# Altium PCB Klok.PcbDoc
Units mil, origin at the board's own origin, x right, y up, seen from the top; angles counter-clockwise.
Board outline 6761 x 3700 mil, 2 copper layers (Top Layer, Bottom Layer); 93 components, 127 nets, 420 pads, 96 vias.
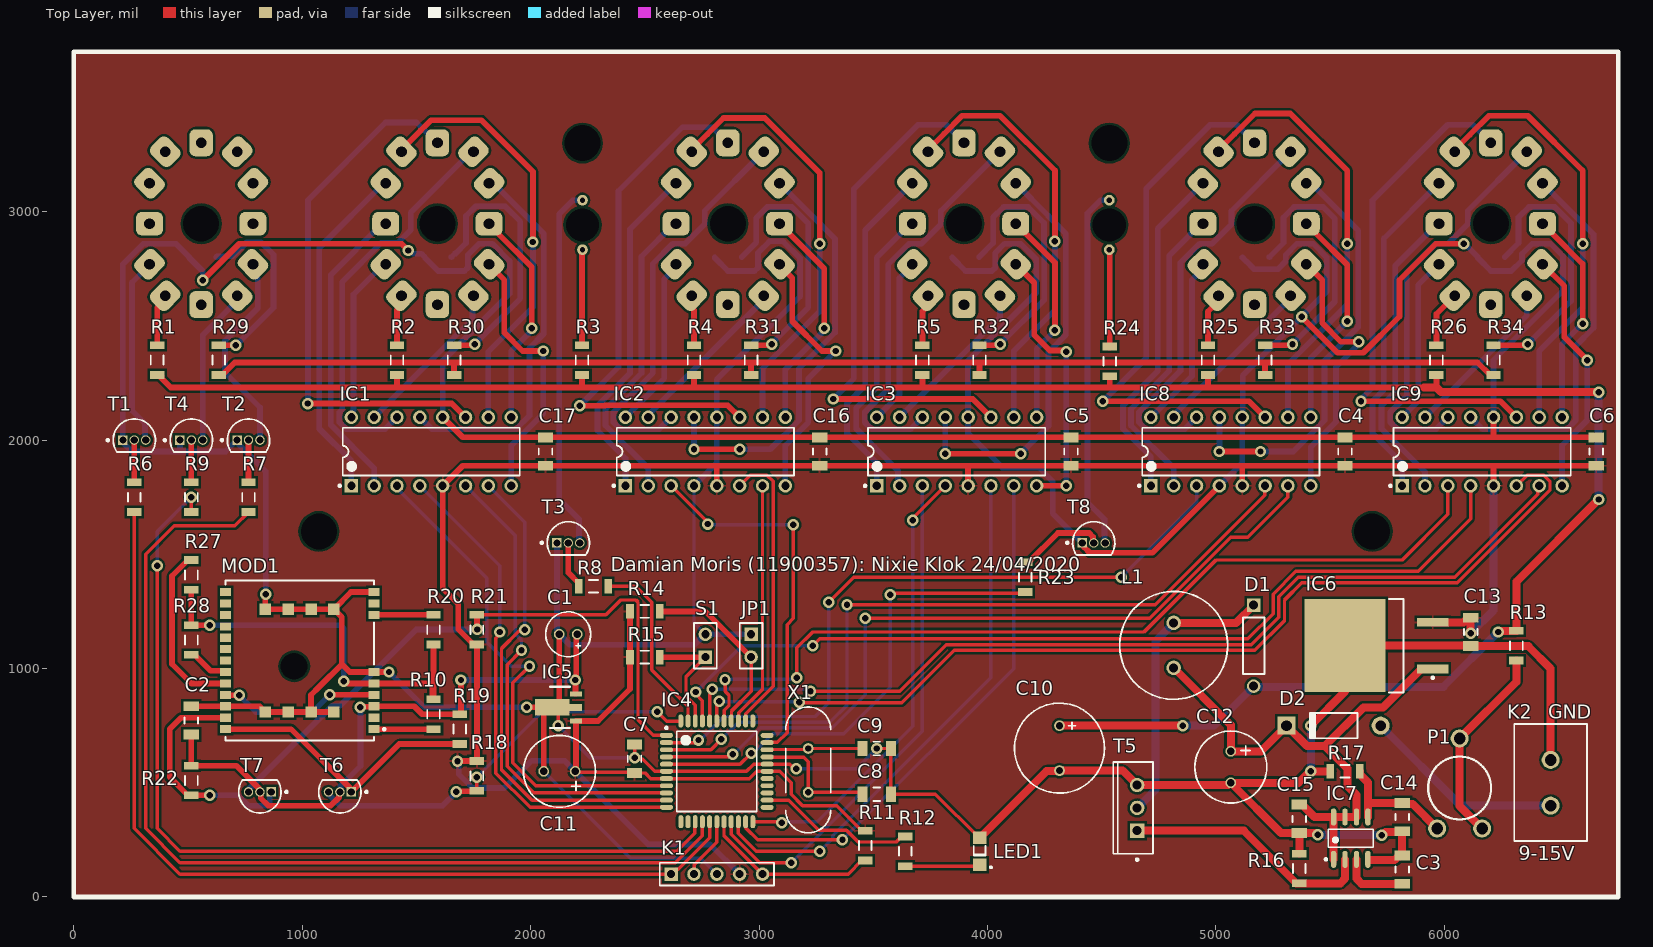
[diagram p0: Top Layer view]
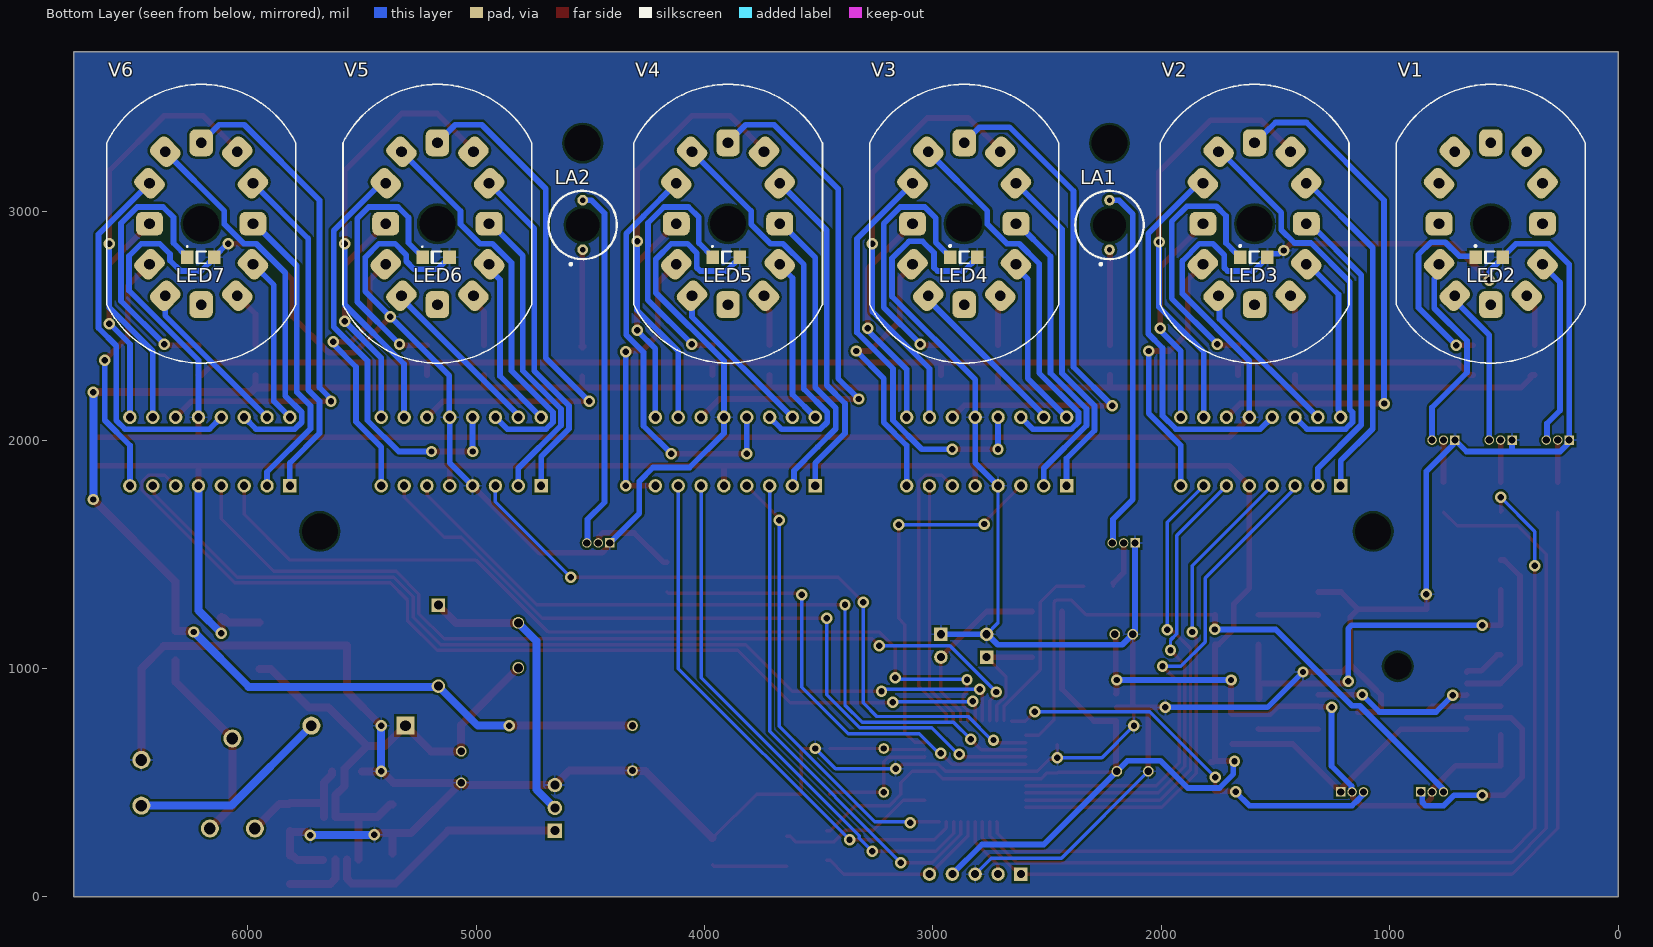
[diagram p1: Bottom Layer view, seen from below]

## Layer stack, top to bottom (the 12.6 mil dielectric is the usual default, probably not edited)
Top Solder: solder mask 0.4, Solder Resist, Dk 3.5
Top Layer: signal copper 1.4
Dielectric 1: dielectric 12.6, FR-4, Dk 4.8
Bottom Layer: signal copper 1.4
Bottom Solder: solder mask 0.4, Solder Resist, Dk 3.5

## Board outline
0,0 6761,0 6761,3700 0,3700

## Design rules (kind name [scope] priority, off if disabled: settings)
Clearance [All] p1: gap=10 ignorepadtopadclearanceinfootprint=TRUE except(0: Arc-Hole Track-Hole SMDPad-Hole THPad-Hole Via-Hole Fill-Hole Poly-Hole Region-Hole Text-Hole)
HoleSize [All] p1: absolutevalues=TRUE maxlimit=200 minlimit=1 maxpercent=80.000 minpercent=20.000
MinimumSolderMaskSliver [All] p1: minsoldermaskwidth=0.5
PolygonConnect [All] p1: connectstyle=Relief reliefconductorwidth=10 reliefentries=4 polygonreliefangle="90 Angle" airgapwidth=10
RoutingVias [All] p1: holewidth=28 width=50 viastyle="Through Hole" minholewidth=28 minwidth=50 maxholewidth=28 maxwidth=50
SilkToSolderMaskClearance [IsPad] p1: minsilkscreentomaskgap=1 clearancetoexposedcopper=TRUE
SolderMaskExpansion [All] p1: expansion=4 istentingtop=FALSE
Width [All] p1: maxlimit=35 minlimit=15 preferedwidth=25 minimp=50.000000 maximp=50.000000 favimp=50.000000
27 further rules are at their usual default settings.

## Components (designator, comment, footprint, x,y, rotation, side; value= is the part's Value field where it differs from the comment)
C1 "Cap Pol1" ELCO2.2 2165,1150 r180 top value=2,2µF
C2 "Cap" 1206_Capacitor 515,772.87 r270 top value=100nF
C3 "Cap" 1206_Capacitor 5815,120 r270 top value=680pF
C4 "Cap" 1206_Capacitor 5565,1950 r270 top value=100nF
C5 "Cap" 1206_Capacitor 4365,1950 r270 top value=100nF
C6 "Cap" 1206_Capacitor 6665,1950 r270 top value=100nF
C7 "Cap" 1206_Capacitor 2455,605 r270 top value=100nF
C8 "Cap" 1206_Capacitor 3515,450 r180 top value=22pF
C9 "Cap" 1206_Capacitor 3515,650 r180 top value=22pF
C10 "Cap Pol1" ELCO10 4315,650 r270 top value=10µF
C11 "Cap Pol1" ELCO100 2195,550 r180 top value=1µF
C12 "Cap Pol1" ELCO100 5065,637.8 r270 top value=100µF
C13 "Cap" 1206_Capacitor 6115,1160 r90 top value=100nF
C14 "Cap" 1206_Capacitor 5815,350 r90 top value=100nF
C15 "Cap" 1206_Capacitor 5365,342.13 r90 top value=100nF
C16 "Cap" 1206_Capacitor 3265,1950 r270 top value=100nF
C17 "Cap" 1206_Capacitor 2065,1950 r270 top value=100nF
D1 "BYV26" Through_Hole 5165,1100 r270 top
D2 "1N4004" DO-41 5515,750 r180 top
IC1 "K155ID1" K155ID1 1565,1950 r90 top
IC2 "K155ID1" K155ID1 2765,1950 r90 top
IC3 "K155ID1" K155ID1 3865,1950 r90 top
IC4 "PIC18F4420" PIC18F4420 2815,550 r0 top
IC5 "AP2205-33Y-13" AP2205-33Y-13 2195,830 r90 top
IC6 "7805" 7805 5562.8,1100 r180 top
IC7 "MC34063" MC34063 5590,257.48 r90 top
IC8 "K155ID1" K155ID1 5065,1950 r90 top
IC9 "K155ID1" K155ID1 6165,1950 r90 top
JP1 "Header 2" HDR1X2 2965,1150 r270 top
K1 "Header 5" HDR1X5 2615,100 r0 top
K2 "Kroonsteen" KROONSTEEN 6465,600 r270 top
L1 "Inductor" Inductor 4815,1003.15 r90 top value=330µH
LA1 "Lamp Neon" Neon_Lamp 2227,3050 r270 bottom locked
LA2 "Lamp Neon" Neon_Lamp 4533,3050 r270 bottom locked
LED1 "LED0" 1206_LED 3965,200 r90 top
LED2 "LED0" 1206_LED 565,2800 r180 bottom
LED3 "LED0" 1206_LED 1595,2800 r180 bottom
LED4 "LED0" 1206_LED 2865,2800 r180 bottom
LED5 "LED0" 1206_LED 3905,2800 r180 bottom
LED6 "LED0" 1206_LED 5175,2800 r180 bottom
LED7 "LED0" 1206_LED 6205,2800 r180 bottom
MOD1 "A2235H" A2235H 963.82,1009.8 r180 top
P1 "RPot" Pot 5968.15,300 r0 top value=500K
R1 "Res2" 1206_Resistor 365,2350 r270 top value=27K
R2 "Res2" 1206_Resistor 1415,2350 r270 top value=27K
R3 "Res2" 1206_Resistor 2225,2350 r270 top value=470K
R4 "Res2" 1206_Resistor 2715,2350 r270 top value=27K
R5 "Res2" 1206_Resistor 3715,2350 r270 top value=27K
R6 "Res2" 1206_Resistor 265,1750 r90 top value=10K
R7 "Res2" 1206_Resistor 765,1750 r90 top value=10K
R8 "Res2" 1206_Resistor 2275,1360 r180 top value=3K3
R9 "Res2" 1206_Resistor 515,1750 r90 top value=10K
R10 "Res2" 1206_Resistor 1575,800 r90 top value=10K
R11 "Res2" 1206_Resistor 3465,225 r90 top value=10K
R12 "Res2" 1206_Resistor 3640,200 r90 top value=1K
R13 "Res2" 1206_Resistor 6315,1100 r90 top value=470K
R14 "Res2" 1206_Resistor 2500,1250 r0 top value=10K
R15 "Res2" 1206_Resistor 2500,1050 r0 top value=10K
R16 "Res2" 1206_Resistor 5365,125 r270 top value=150
R17 "Res2" 1206_Resistor 5565,550 r0 top value=5K6
R18 "Res2" 1206_Resistor 1765,530 r90 top value=10K
R19 "Res2" 1206_Resistor 1690,735 r90 top value=10K
R20 "Res2" 1206_Resistor 1575,1170 r270 top value=10K
R21 "Res2" 1206_Resistor 1765,1170 r270 top value=10K
R22 "Res2" 1206_Resistor 515,510 r90 top value=10K
R23 "Res2" 1206_Resistor 4165,1400 r90 top value=3K3
R24 "Res2" 1206_Resistor 4535,2345 r270 top value=470K
R25 "Res2" 1206_Resistor 4965,2350 r270 top value=27K
R26 "Res2" 1206_Resistor 5965,2350 r270 top value=27K
R27 "Res2" 1206_Resistor 515,1410 r270 top value=2,2K
R28 "Res2" 1206_Resistor 515,1125 r90 top value=2,2K
R29 "Res2" 1206_Resistor 635,2350 r90 top value=180
R30 "Res2" 1206_Resistor 1665,2350 r90 top value=180
R31 "Res2" 1206_Resistor 2965,2350 r90 top value=180
R32 "Res2" 1206_Resistor 3965,2350 r90 top value=180
R33 "Res2" 1206_Resistor 5215,2350 r90 top value=180
R34 "Res2" 1206_Resistor 6215,2350 r90 top value=180
S1 "Switch" HDR1X2 2765,1050 r90 top
T1 "MPSA42" MPSA42 265,2000 r0 top
T2 "MPSA42" MPSA42 765,2000 r0 top
T3 "MPSA42" MPSA42 2165,1550 r0 top
T4 "MPSA42" MPSA42 515,2000 r0 top
T5 "SPP20N60C3" SPP20N60C3 4655,390 r180 top
T6 "2N7000" 2N7000 1165,460 r180 top
T7 "2N7000" 2N7000 815,460 r180 top
T8 "MPSA42" MPSA42 4465,1550 r0 top
V1 "Nixie IN12" "Nixie IN12" 556,2950 r180 bottom locked
V2 "Nixie IN12" "Nixie IN12" 1590,2950 r180 bottom locked
V3 "Nixie IN12" "Nixie IN12" 2861,2950 r180 bottom locked
V4 "Nixie IN12" "Nixie IN12" 3895,2950 r180 bottom locked
V5 "Nixie IN12" "Nixie IN12" 5167,2950 r180 bottom locked
V6 "Nixie IN12" "Nixie IN12" 6201,2950 r180 bottom locked
X1 "22.1184MHz" "XTAL - duplicate" 3215,457.87 r90 top

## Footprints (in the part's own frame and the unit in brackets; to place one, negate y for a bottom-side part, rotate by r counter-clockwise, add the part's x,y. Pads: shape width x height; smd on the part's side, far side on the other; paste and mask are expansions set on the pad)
2N7000 [mm]
  rect 1.05x1.05 hole 0.8: 1(-1.27,0)
  round 1.05 hole 0.8: 2(0,0) 3(1.27,0)
  silkscreen extent -3.08,-1.34 2.35,2.35, body extent -2.35,-1.33 2.36,2.36, height 7.87
1206_Capacitor [mm]
  rect 1.1x1.7 smd: 1(-1.578,0) 2(1.578,0)
  silkscreen extent -0.35,-0.75 0.35,0.75, body extent -1.7,-0.9 1.7,0.9, height 1.52
1206_LED [mm]
  rect 1.4x1.5 smd: 1(-1.5,0) 2(1.5,0)
  silkscreen extent -0.5,-0.67 0.6,0.65, body extent -1.6,-0.8 1.6,0.8, height 0.68
1206_Resistor [mm]
  rect 0.85x1.6 smd: 1(-1.651,0) 2(1.651,0)
  silkscreen extent -0.5,-0.7 0.5,0.7, body extent -1.6,-0.85 1.6,0.85, height 0.65
7805 [mm]
  rect 3.5x0.95 smd: 1(-9.804,2.591) 3(-9.804,-2.591)
  rect 9x10.35 smd: 4(-0.056,0)
  silkscreen extent -9.93,-5.2 -4.96,5.2, body extent -6.56,-5.2 2.79,5.2, height 4.6
A2235H [mm]
  rect 1.2x0.9 smd: 1(-8.89,6.985) 2(-8.89,5.715) 3(-8.89,4.445) 4(-8.89,3.175) 5(-8.89,1.905) 6(-8.89,0.635) 7(-8.89,-5.715) 8(-8.89,-6.985) 9(-8.89,-8.255) 10(7.62,-8.255) 11(7.62,-6.985) 12(7.62,-5.715) 13(7.62,-4.445) 14(7.62,-3.175) 15(7.62,-1.905) 16(7.62,-0.635) 17(7.62,0.635) 18(7.62,1.905) 19(7.62,3.175) 20(7.62,4.445) 21(7.62,5.715) 22(7.62,6.985)
  rect 1.27x1.27 smd: 23(-4.445,5.08) 24(-1.905,5.08) 25(0.635,5.08) 26(3.175,5.08) 27(-4.445,-6.35) 28(-1.905,-6.35) 29(0.635,-6.35) 30(3.175,-6.35)
  round 2.7 hole 3 unplated: ""(-0.03,-0.005)
  silkscreen extent -10.16,-9.53 7.62,8.26, body extent -8.89,-9.52 7.62,8.25, height 7.11
AP2205-33Y-13 [mm]
  rect 0.55x1.3 smd: 1(-1.5,-0.088) 3(1.5,-0.088)
  rect 1.85x3.825 smd: 2(0,2.54)
  rect 0.8x1.475 smd: 2(0,0)
  silkscreen extent -2.3,0.6 2.3,2.8
DO-41 [mm] "Diode, Axial; Body 5.2 x 2.7 mm (LxDia. max), Lead Dia. 0.86 mm (max)"
  round 2 hole 1.2: 1(-5.23,0)
  rect 2x2 hole 1.2: 2(5.23,0)
  silkscreen extent -2.65,-1.4 2.75,1.4
ELCO2.2 [mm]
  round 1.2 hole 0.8: 1(-0.984,0) 2(1.016,0)
  silkscreen extent -2.48,-2.5 2.51,2.5
ELCO10 [mm]
  round 1.2 hole 0.8: 1(-2.54,0) 2(2.46,0)
  silkscreen extent -5.04,-5 4.96,5
ELCO100 [mm]
  round 1.2 hole 0.8: 1(0,0) 2(3.5,0)
  silkscreen extent -2.25,-4 5.75,4
HDR1X2 [mm] "Connector; Header; 2 Position"
  rect 1.5x1.5 hole 0.9: 1(0,0)
  round 1.5 hole 0.9: 2(2.54,0)
  silkscreen extent -1.27,-1.27 3.81,1.27
HDR1X5 [mm] "Connector; Header; 5 Position"
  rect 1.5x1.5 hole 0.9: 1(0,0)
  round 1.5 hole 0.9: 2(2.54,0) 3(5.08,0) 4(7.62,0) 5(10.16,0)
  silkscreen extent -1.27,-1.27 11.43,1.27
Inductor [mm]
  round 1.6 / inner round 1.2 / far side round 1.3 hole 1: 1(0,0) 2(5,0)
  silkscreen extent -3.5,-6 8.5,6
K155ID1 [mm]
  rect 1.5x1.5 hole 0.9: 1(-3.81,8.89)
  round 1.5 hole 0.9: 2(-3.81,6.35) 3(-3.81,3.81) 4(-3.81,1.27) 5(-3.81,-1.27) 6(-3.81,-3.81) 7(-3.81,-6.35) 8(-3.81,-8.89) 9(3.81,-8.89) 10(3.81,-6.35) 11(3.81,-3.81) 12(3.81,-1.27) 13(3.81,1.27) 14(3.81,3.81) 15(3.81,6.35) 16(3.81,8.89)
  silkscreen extent -3.93,-9.85 2.65,10.31, body extent -3.95,-9.85 3.95,9.85, height 5.08
KROONSTEEN [mm]
  round 2 / inner round 1.2 / far side round 2 hole 1.3: 1(0,0) 2(5.08,0)
  silkscreen extent -4,-4.05 9,4.05
MC34063 [mm]
  oval 1.9x0.6 smd: 1(-2.35,1.905) 2(-2.35,0.635) 3(-2.35,-0.635) 4(-2.35,-1.905) 5(2.35,-1.905) 6(2.35,-0.635) 7(2.35,0.635) 8(2.35,1.905)
  silkscreen extent -2.47,-2.5 1,2.88, body extent -2,-2.5 2,2.5, height 1.75
MPSA42 [mm]
  rect 1.05x1.05 hole 0.8: 1(-1.27,0)
  round 1.05 hole 0.8: 2(0,0) 3(1.27,0)
  silkscreen extent -3.07,-1.34 2.35,2.35, body extent -2.35,-1.33 2.36,2.36, height 7.87
Neon_Lamp [mm]
  round 1.2 hole 0.6: 1(0,0) 2(5.5,0)
  round 1.524 hole 3.7: 3(2.75,0)
  silkscreen extent -1.05,-3.8 6.55,3.8
"Nixie IN12" [mm]
  rrect50% 0x0 hole 4 unplated: 0(-0.05,-0.075)
  rrect50% 2.6x3 hole 1.2 rot 45: 1(3.95,-8.075) 2(5.7,-4.575) 7(-4.05,7.925) 8(-5.8,4.425)
  rrect50% 3x2.6 hole 1.2: 3(5.7,-0.075) 9(-5.8,-0.075)
  rrect50% 2.6x3 hole 1.2 rot 135: 4(5.7,4.425) 5(3.95,7.925) 10(-5.8,-4.575) 11(-4.05,-8.075)
  rrect50% 2.6x3 hole 1.2: 6(-0.05,8.925) 12(-0.05,-9.075)
  silkscreen extent -10.55,-15.58 10.45,15.42
PIC18F4420 [mm]
  oval 1.45x0.55 smd: 1(-5.6,4) 2(-5.6,3.2) 3(-5.6,2.4) 4(-5.6,1.6) 5(-5.6,0.8) 6(-5.6,0) 7(-5.6,-0.8) 8(-5.6,-1.6) 9(-5.6,-2.4) 10(-5.6,-3.2) 11(-5.6,-4) 23(5.6,-4) 24(5.6,-3.2) 25(5.6,-2.4) 26(5.6,-1.6) 27(5.6,-0.8) 28(5.6,0) 29(5.6,0.8) 30(5.6,1.6) 31(5.6,2.4) 32(5.6,3.2) 33(5.6,4)
  oval 0.55x1.45 smd: 12(-4,-5.6) 13(-3.2,-5.6) 14(-2.4,-5.6) 15(-1.6,-5.6) 16(-0.8,-5.6) 17(0,-5.6) 18(0.8,-5.6) 19(1.6,-5.6) 20(2.4,-5.6) 21(3.2,-5.6) 22(4,-5.6) 34(4,5.6) 35(3.2,5.6) 36(2.4,5.6) 37(1.6,5.6) 38(0.8,5.6) 39(0,5.6) 40(-0.8,5.6) 41(-1.6,5.6) 42(-2.4,5.6) 43(-3.2,5.6) 44(-4,5.6)
  silkscreen extent -5.72,-4.45 4.45,4.95, body extent -5,-5 5,5, height 1.2
Pot [mm]
  round 2 / inner round 1.2 / far side round 2 hole 1.3: 1(2.5,10) 2(0,0) 3(5,0)
  silkscreen extent -1,1 6,8
SPP20N60C3 [mm]
  rect 1.6x1.6 hole 1: 1(0,2.54)
  round 1.6 hole 1: 2(0,0) 3(0,-2.54)
  silkscreen extent -1.75,-5.1 2.65,5.87, body extent -1.75,-5.1 2.65,5.1, height 20.7
Through_Hole [mm]
  rect 1.5x1.5 hole 1: 1(-4.5,0)
  round 1.5 hole 1: 2(4.5,0)
  silkscreen extent -3.15,-1.2 3.15,1.2, body extent -3.15,-1.2 3.15,1.2, height 2.4
"XTAL - duplicate" [mm]
  round 1.2 hole 0.7: 1(0,0) 2(4.88,0)
  silkscreen extent -4.5,-2.5 9.5,2.5

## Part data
C1 C10 C11 C12: "Polarized Capacitor (Radial)"
C2 C3 C4 C5 C6 C7 C8 C9 C13 C14 C15 C16 C17: "Capacitor"
D2: library part "Diode 1N4004", "1 Amp General Purpose Rectifier"
JP1: "Header, 2-Pin"
K1: "Header, 5-Pin"
K2 S1: library part "Header 2", "Header, 2-Pin"
LA1 LA2: "Neon Lamp"
LED1 LED2 LED3 LED4 LED5 LED6 LED7: "Typical INFRARED GaAs LED"
P1: "Potentiometer"
R1 R2 R3 R4 R5 R6 R7 R8 R9 R10 R11 R12 R13 R14 R15 R16 R17 R18 R19 R20 R21 R22 R23 R24 R25 R26 R27 R28 R29 R30 R31 R32 R33 R34: "Resistor"
X1: library part XTAL, "Crystal Oscillator"

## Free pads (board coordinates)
  round 60 hole 157.48 unplated: 4(1073,1600) 4(2227,3300) 4(4533,3300) 4(5684,1600)

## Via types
v1: diameter 50, hole 28, Top Layer to Bottom Layer, 96 vias

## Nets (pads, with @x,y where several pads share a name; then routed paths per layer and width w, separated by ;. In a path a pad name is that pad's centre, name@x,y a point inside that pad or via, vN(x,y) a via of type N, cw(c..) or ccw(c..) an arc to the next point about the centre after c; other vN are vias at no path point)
+1.8V: MOD1.5 R10.2 R20.2 R27.2 R28.2 | length 1754.3
  Top Layer w25: R27.2 R28.2 v1(595,1190) ; v1(1182.47,944.64) 1189.23,944.64 1199.07,934.8 MOD1.5 ; MOD1.5@1319.72,934.8 1565.2,934.8 1570,930 1570,869.23 1574.23,865 R10.2 R20.2
  Bottom Layer w25: v1(595,1190) 1167.57,1190 1182.22,1175.36 1182.22,944.89 v1(1182.47,944.64)
+3,3V: C1.1 C2.2 IC5.3 MOD1.3 R19.2 R22.2 T6.2 T7.2 | length 2691.6
  Top Layer w25: C2.2 R22.2 711.05,575 811.87,474.18 811.87,463.13 818.13,456.87 818.13,433.72 851.84,400 1125,400 1161.87,436.87 1161.87,456.87 T6.2 ; v1(1255,830) 1257.4,832.4 1311.42,832.4 MOD1.3 1490.46,834.8 1525.27,800 R19.2 1695,805 v1(1695,950) ; IC5.3 2196.72,890.73 2196.72,948.28 v1(2195,950) 2199.48,954.48 2199.48,1145.74 C1.1
  Bottom Layer w25: T6.2 1168.13,463.13 1168.13,486.28 1255,573.16 v1(1255,830) ; v1(1695,950) v1(2195,950)
+3.3V: R29.1 R30.1 R31.1 R32.1 R33.1 R34.1 | length 5845.6
  Top Layer w25: R29.1 649.76,2285 704.76,2340 1665,2340 ; R30.1 1665,2340 ; R31.1 2965,2340 ; R32.1 3965,2340 ; R33.1 5215,2340 ; R34.1 6200.24,2285 6145.24,2340 5215,2340 ; 1665,2340 2965,2340 ; 2965,2340 3965,2340 ; 3965,2340 5215,2340
+5V: C4.2 C5.2 C6.2 C7.2 C11.1 C13.2 C16.2 C17.2 IC1.5 IC2.5 IC3.5 IC4.7 IC4.28 IC5.1 IC6.3 IC8.5 IC9.5 K1.4 R11.2 R14.1 R15.1 R18.2 R21.2 | length 11606.5
  Top Layer w15: C11.1 2198.56,546.44 2451.44,546.44 C7.2@2455.05,542.82 ; C7.2 C7.2@2455.05,542.82 ; IC4.7 2526.5,518.5 2502.18,542.82 C7.2@2455.05,542.82 ; IC4.7@2595.8,517.23 2957.23,517.23 2990,550 IC4.28 3090,550 3140,500 3140,450 3190,400 3340.24,400 3450.24,290 R11.2
  Top Layer w25: v1(1680,595) R18.2 R21.2 1750.24,1105 1683.76,1171.48 1683.76,1281.24 1615,1350 IC1.5 1702.87,1887.87 C17.2 2815,1887.87 ; R18.2@1770,595 1774.23,590.77 R18.2@1784,590.77 ; C11.1@2198.44,550 IC5.1 2199.39,770 2295,770 2435,910 R15.1 R14.1 ; IC2.5 2815,1887.87 ; IC3.5 3915,1887.87 ; IC8.5 5115,1887.87 ; IC9.5 6215,1887.87 ; C6.2 6215,1887.87 ; 2815,1887.87 C16.2 3915,1887.87 ; 3915,1887.87 C5.2 5115,1887.87 ; 5115,1887.87 C4.2 6215,1887.87
  Top Layer w35: IC6.3 6083.06,1202 6103.19,1222.13 C13.2 v1(6115,1154.53) ; C13.2@6115,1226.28 C13.2@6119.15,1222.13
  Bottom Layer w25: v1(1680,595) 1684.78,590.22 1684.78,538.04 1745.32,477.5 1884.78,477.5 2003.4,596.12 2148.88,596.12 C11.1 2515,230 2785,230 K1.4
  Bottom Layer w35: v1(6115,1154.53) 6215,1254.53 IC9.5
+180V: C10.1 D1.2 R1.2 R2.2 R3.2 R4.2 R5.2 R13.2 R24.2 R25.2 R26.2 | length 10105.3
  Top Layer w25: R1.2 379.76,2285 384,2280.77 384,2271 425,2230 1415,2230 ; R2.2 1415,2230 ; R3.2 2225,2230 ; R4.2 2715,2230 ; R5.2 3715,2230 ; R24.2 4535,2230 ; R25.2 4965,2240 4975,2230 ; 5911.36,2230 4975,2230 ; 5965,2230 R26.2 ; 1415,2230 2225,2230 ; 2225,2230 2715,2230 ; 2715,2230 3715,2230 ; 3715,2230 4535,2230 ; 4535,2230 4965,2230 4975,2230
  Top Layer w35: C10.1 v1(4855,750) ; D1.2 5167.83,920 D1.2@5169.25,921.42 ; 5911.36,2230 5965,2230 5985,2210 v1(6675,2210) ; v1(6235,1160) 6239.06,1160 6244.06,1165 R13.2 6315,1380 v1(6675,1740)
  Bottom Layer w35: v1(4855,750) 4992.17,750 D1.2 5167.83,920 5995,920 v1(6235,1160) ; v1(6675,1740) v1(6675,2210)
GND: C1.2 C2.1 C3.1 C4.1 C5.1 C6.1 C7.1 C8.1 C9.1 C10.2 C11.2 C12.2 C13.1 C14.1 C15.1 C16.1 C17.1 IC1.12 IC2.4 IC2.12 IC3.12 IC4.6 IC4.29 IC5.2 IC6.4 IC7.4 IC8.4 IC8.12 IC9.12 JP1.1 K1.3 K2.1 LED1.2 LED2.2 LED3.2 LED4.2 LED5.2 LED6.2 LED7.2 MOD1.6 MOD1.9 MOD1.20 MOD1.23 MOD1.24 MOD1.25 MOD1.26 MOD1.27 MOD1.28 MOD1.29 MOD1.30 R16.1 R17.1 S1.2 T1.1 T2.1 T3.1 T4.1 T5.3 T8.1 | length 32496
  Top Layer w15: v1(2120,750) IC5.2@2120,830 ; C7.1 v1(2455,610) 2461.7,603.3 2490.18,603.3 2543.48,550 IC4.6 2945,550 2976.5,581.5 3133.5,581.5 3146.76,568.24 3156.86,568.24 v1(3163.56,561.55) ; v1(3514.95,650.05) 3515,650 C9.1 C8.1 3772.09,450 3963.03,259.06 LED1.2
  Top Layer w25: C2.1 515.1,834.9 663.72,834.9 663.82,835 813.62,835 MOD1.26 MOD1.25 MOD1.24 ; v1(565,2700) 724.73,2859.73 1435.27,2859.73 v1(1465,2830) ; v1(840,1325) 838.82,1323.82 MOD1.30 MOD1.29 MOD1.28 MOD1.27 ; MOD1.23 MOD1.24 ; MOD1.9 1213.82,1334.8 MOD1.27 ; v1(1380.2,984.8) MOD1.6 1207.83,984.8 1173.82,1018.82 ; IC1.12 1702.87,2012.13 C17.1 C16.1 C5.1 C4.1 6215,2012.13 ; v1(1982.5,830) IC5.2@2055,830 ; C11.2 2057.2,822.03 2060.65,825.47 2056.12,830 2095,830 2115,830 2125,840 C1.2 ; IC5.2@2120,830 IC5.2@2195,830 ; T8.1 4421.83,1543.17 4421.83,1532.12 4447.12,1506.83 4721.83,1506.83 IC8.4 ; v1(5375,2540) 5532.5,2382.5 5644.68,2382.5 5803.46,2541.28 5803.46,2700.95 5962.51,2860 v1(6085,2860) ; IC9.12 6215,2012.13 ; C6.1 6215,2012.13 ; MOD1.24 1038.82,883.82 1075,920 1173.82,1018.82 ; MOD1.27 1173.82,1224.8 1173.82,1018.82
  Top Layer w35: LED1.2 3966.97,259.06 4258.72,550.81 4312.66,550.81 C10.2 4591.85,553.15 T5.3 5051.69,490 5061.69,500 C12.2 ; R16.1 C15.1 ; v1(5415,750) 5565,900 IC6.4 6112.87,1100 C13.1 6367.13,1097.87 6465,1000 K2.1 ; v1(5445,272.13) 5437.13,280 C15.1 ; R17.1 v1(5415,550) 5410.94,550 5360.94,500 C12.2 ; IC7.4@5670.69,161.29 5782.35,161.29 5803.19,182.13 C3.1 C14.1 5810.85,283.72 5742.78,283.72 5729.06,270 v1(5725,270) ; C12.2 5285,280 C15.1
  Bottom Layer w15: C11.2 2437.2,170 2745,170 K1.3 ; v1(2120,750) 2260,610 v1(2455,610) ; IC2.4 2715,1200 S1.2 ; v1(3163.56,561.55) 3426.44,561.55 v1(3514.95,650.05)
  Bottom Layer w25: T4.1 465,1955.53 459.47,1950 ; v1(565,2700) 565,2738.98 505.94,2798.03 LED2.2 505.94,2801.97 448.18,2859.73 304.73,2859.73 215,2770 T1.1 221.83,1993.17 221.83,1982.12 253.95,1950 459.47,1950 ; v1(840,1325) 840,1863.95 721.83,1982.12 721.83,1993.17 T2.1 665,1950 459.47,1950 ; v1(1380.2,984.8) 1535,830 v1(1982.5,830) ; v1(1465,2830) 1471.76,2830 1485.45,2816.32 1520.89,2816.32 1535.94,2801.26 LED3.2 1595.94,2740 1710.36,2740 1725,2754.64 1725,2810 1775,2860 1832.43,2860 1908.2,2784.23 1908.2,2640.37 1615,2347.18 IC1.12 ; T3.1 2115,1166.02 2125,1156.02 C1.2 2171.12,1103.88 2716.33,1103.88 2762.45,1150 S1.2 JP1.1 ; IC2.4 2815,1900 IC2.12 2815,2264.63 3179.2,2628.82 3179.2,2795.8 3105,2870 3045,2870 2995,2820 2995,2754.64 2980.36,2740 2863.98,2740 2805.94,2798.03 LED4.2 ; LED5.2 3845.94,2798.03 3903.98,2740 4018.85,2740 4033.5,2754.64 4033.5,2818.5 4075,2860 4145,2860 4213.2,2791.8 4213.2,2645.37 3915,2347.18 IC3.12 3915,2030 4065,1880 4225,1880 4285,1820 4285,1680 T8.1 ; IC8.4 5115,1900 IC8.12 5117.4,2102.4 5117.4,2282.4 v1(5375,2540) 5485.2,2650.2 5485.2,2799.8 5425,2860 5355,2860 5305.5,2810.5 5305.5,2782.54 5270.93,2747.97 5197.18,2747.97 ; LED6.2 5115.94,2798.03 5131,2782.97 5132.97,2782.97 5167.94,2748.01 5197.14,2748.01 ; v1(6085,2860) 6087.91,2860 6145.94,2801.97 LED7.2 6145.94,2798.03 6203.98,2740 6292.96,2740 6339.5,2786.54 6339.5,2814.5 6385,2860 6465,2860 6519.2,2805.8 6519.2,2654.2 6215,2350 IC9.12
  Bottom Layer w35: v1(5415,550) v1(5415,750) ; v1(5445,272.13) 5446.06,271.06 5723.94,271.06 v1(5725,270)
NetC3_2: C3.2 IC7.3 | length 293.8
  Top Layer w35: IC7.3 5615,80.5 5637.63,57.87 C3.2
NetC8_2: C8.2 IC4.30 X1.1 | length 563.4
  Top Layer w15: IC4.30 3036.75,611.72 3195.13,611.72 3215,591.84 X1.1 3445,457.87 C8.2
NetC9_2: C9.2 IC4.31 X1.2 | length 419.7
  Top Layer w15: IC4.31 3036.75,645.76 3210.76,645.76 X1.2 C9.2
NetC12_1: C12.1 C15.2 D2.2 IC6.1 IC7.1 IC7.6 IC7.7 IC7.8 L1.1 | length 2399.2
  Top Layer w35: L1.1 5065,753.15 C12.1 5196.89,637.8 D2.2 5398.59,660.51 5476.61,660.51 ; C15.2 5376.81,404.25 5431.06,350 IC7.7 IC7.6 5615,446.01 5575,486.01 5575,562.12 5476.61,660.51 ; IC7.1 IC7.8@5515,347.82 ; IC6.1 5898.6,998 5730.6,830 5646.1,830 5476.61,660.51
NetC14_2: C14.2 IC7.5 P1.2 R17.2 | length 565
  Top Layer w35: R17.2 5630,536.77 5665,501.77 5665,410 ; IC7.5 5665,410 ; P1.2 5860.18,407.97 5819.15,407.97 C14.2 5667.13,412.13 5665,410
NetD1_1: D1.1 L1.2 T5.2 | length 1258.2
  Top Layer w35: L1.2 5087.83,1200 D1.1
  Bottom Layer w35: T5.2 4736.13,471.13 4736.13,1121.13 L1.2
NetD2_1: D2.1 K2.2 | length 889.1
  Bottom Layer w35: D2.1 6070.91,400 K2.2
NetIC1_1: IC1.1 V2.4 | length 1503.2
  Bottom Layer w25: IC1.1 1215,1910 1075,2050 1075,2842.17 V2.4@1360,3127.17
NetIC1_2: IC1.2 V2.3 | length 1330.7
  Bottom Layer w25: IC1.2 1315,1876.92 1125,2066.92 1125,2722.87 1352.13,2950 V2.3@1360,2950
NetIC1_3: IC1.3 IC4.8 | length 2243.4
  Top Layer w15: v1(1995,1010) 1922.5,937.5 1922.5,587.5 2022.99,487.01 IC4.8
  Bottom Layer w15: IC1.3 1415,1790 1808.59,1396.41 1808.59,1116.31 1914.9,1010 v1(1995,1010)
NetIC1_4: IC1.4 IC4.11 | length 2218.8
  Top Layer w15: v1(1864.95,1160.05) 1864.95,1150.58 1847.5,1133.13 1847.5,542.5 1997.48,392.52 IC4.11
  Bottom Layer w15: IC1.4 1864.95,1450.05 v1(1864.95,1160.05)
NetIC1_6: IC1.6 IC4.9 | length 2100.4
  Top Layer w15: v1(1960,1080) 1897.5,1017.5 1897.5,572.5 2014.49,455.51 IC4.9
  Bottom Layer w15: IC1.6 1932.5,1582.5 1932.5,1152.4 1960,1124.9 v1(1960,1080)
NetIC1_7: IC1.7 IC4.10 | length 2140.3
  Top Layer w15: v1(1975,1170) 1968.3,1163.3 1948.2,1163.3 1872.5,1087.6 1872.5,557.5 2005.98,424.02 IC4.10
  Bottom Layer w15: IC1.7 1975,1640 v1(1975,1170)
NetIC1_8: IC1.8 V2.10 | length 1183.9
  Top Layer w25: V2.10@1812.76,2772.83 1885,2700.59 1885,2470 1965,2390 v1(2055,2390)
  Bottom Layer w25: IC1.8 1915,1976.92 2055,2116.92 v1(2055,2390)
NetIC1_9: IC1.9 V2.9 | length 967.4
  Top Layer w25: V2.9@1812.76,2950 1813.55,2950 1851.23,2912.32 1851.23,2911.53 2005,2757.76 v1(2005,2490)
  Bottom Layer w25: IC1.9 1915,2390 2005,2480 v1(2005,2490)
NetIC1_10: IC1.10 V2.5 | length 1886.2
  Top Layer w25: V2.5@1428.9,3264.96 1518.29,3354.35 1518.29,3354.76 1546.46,3382.93 1546.87,3382.93 1563.94,3400 1785,3400 2010,3175 v1(2010,2867)
  Bottom Layer w25: IC1.10 1815,2387.23 2010,2582.23 v1(2010,2867)
NetIC1_11: IC1.11 V2.6 | length 2343
  Top Layer w25: v1(1025,2160) 1655,2160 IC1.11
  Bottom Layer w25: v1(1025,2160) 1025,3050 1365,3390 1500.71,3390 1547.9,3342.8 1548.69,3342.8 1586.38,3305.12 V2.6@1586.38,3304.33
NetIC1_13: IC1.13 V2.8 | length 1679.6
  Bottom Layer w25: IC1.13 1567.03,2047.97 1936.55,2047.97 1995,2106.42 1995,2402.82 2057.5,2465.32 2057.5,2904 1995,2966.5 1837.28,3124.21 V2.8
NetIC1_14: IC1.14 V2.7 | length 1755.5
  Bottom Layer w25: IC1.14 1362.97,2047.97 1193.45,2047.97 1162.97,2078.45 1162.97,2121.55 1175,2133.58 1175,2692.04 1345.65,2862.68 1417.68,2862.68 1475,2920 1475,2996.1 V2.7@1743.86,3264.96
NetIC1_15: IC1.15 V2.11 | length 713.8
  Bottom Layer w25: IC1.15 1745.19,2530.19 1745.19,2633.71 V2.11@1743.86,2635.04
NetIC1_16: IC1.16 V2.2 | length 732.9
  Bottom Layer w25: IC1.16 1221.52,2106.52 1221.52,2128.19 1225,2131.67 1225,2637.83 V2.2@1360,2772.83
NetIC2_1: IC2.1 V3.4 | length 1517.1
  Bottom Layer w25: IC2.1 2415,1920 2292.97,2042.03 2292.97,2150.55 2435,2292.57 2435,2922.62 V3.4
NetIC2_2: IC2.2 V3.3 | length 1357
  Bottom Layer w25: IC2.2 2515,1876.92 2327.97,2063.95 2327.97,2136.05 2485,2293.08 2485,2803.33 2628.72,2947.05 V3.3
NetIC2_3: IC2.3 IC4.32 | length 1637.3
  Top Layer w15: IC2.3 2775,1640 v1(2775,1632.5) ; IC4.32 3036.75,677.26 3080.38,677.26 3122.45,719.33 3122.45,1192.45 3150.3,1220.3 v1(3150.3,1630)
  Bottom Layer w15: v1(2775,1632.5) 2777.5,1630 v1(3150.3,1630)
NetIC2_6: IC2.6 IC4.35 | length 1277.1
  Top Layer w15: IC2.6 2962.03,1847.03 3034.48,1847.03 3062.03,1819.48 3062.03,921.67 2942.26,801.9 2942.26,771.75 IC4.35
NetIC2_7: IC2.7 IC4.36 | length 1073.2
  Top Layer w15: IC4.36 2910.76,771.75 2910.76,805.76 3015,910 IC2.7
NetIC2_8: IC2.8 V3.10 | length 1197.9
  Top Layer w25: V3.10 3089.35,2765.35 3145,2709.7 3145,2520 3275,2390 v1(3335,2390)
  Bottom Layer w25: IC2.8 3115,1976.92 3215,2076.92 3215,2270 v1(3335,2390)
NetIC2_9: IC2.9 V3.9 | length 999
  Top Layer w25: V3.9 3090.14,2947.05 3127.82,2909.36 3127.82,2908.57 3285,2751.39 v1(3285,2490)
  Bottom Layer w25: IC2.9 3115,2310 3285,2480 v1(3285,2490)
NetIC2_10: IC2.10 V3.5 | length 1899
  Top Layer w25: V3.5 2705.49,3270.49 2774.8,3339.8 2774.8,3340.27 2844.53,3410 3025,3410 3265,3170 v1(3265,2860)
  Bottom Layer w25: IC2.10 3015,2312.82 3265,2562.82 v1(3265,2860)
NetIC2_11: IC2.11 V3.6 | length 2355.6
  Top Layer w25: v1(2215,2150) 2325,2150 2327.03,2152.03 2862.97,2152.03 IC2.11
  Bottom Layer w25: v1(2215,2150) 2385,2320 2385,3090 2665,3370 2795.14,3370 2862.97,3302.17 V3.6
NetIC2_13: IC2.13 V3.8 | length 1856.1
  Top Layer w25: v1(2715,1960) v1(2915,1960)
  Bottom Layer w25: v1(2715,1960) IC2.13 ; v1(2915,1960) 3048.58,1960 3175,2086.42 3175,2312.82 3332.5,2470.32 3332.5,2881.06 V3.8
NetIC2_14: IC2.14 V3.7 | length 1773.8
  Bottom Layer w25: IC2.14 2562.97,2047.97 2393.45,2047.97 2362.97,2078.45 2362.97,2121.55 2535,2293.58 2535,2772.49 2622.24,2859.73 2676.34,2859.73 2761.73,2945.12 2761.73,3003.29 V3.7
NetIC2_15: IC2.15 V3.11 | length 741.5
  Bottom Layer w25: IC2.15 2515,2109.22 3020.45,2614.66 V3.11
NetIC2_16: IC2.16 V3.2 | length 761.7
  Bottom Layer w25: IC2.16 2585,2270 2585,2705.63 2636.59,2757.22 V3.2
NetIC3_1: IC3.1 V4.4 | length 1496.4
  Bottom Layer w25: IC3.1 3515,1900 3385,2030 3385,2160 3465,2240 3465,2918.62 V4.4
NetIC3_2: IC3.2 V4.3 | length 1332.1
  Bottom Layer w25: IC3.2 3608.48,1806.52 3608.48,1865.73 3505,1969.22 3505,1970 3425,2050 3425,2140 3515,2230 3515,2799.33 3662.72,2947.05 V4.3
NetIC3_3: IC3.3 IC4.19 | length 2256.7
  Top Layer w15: IC4.19 2877.99,274.62 3002.62,150 v1(3140,150)
  Bottom Layer w15: v1(3140,150) 3715,725 IC3.3
NetIC3_4: IC3.4 IC4.22 | length 1988.5
  Top Layer w15: IC4.22 3094.53,329.53 3099.11,324.95 v1(3100.05,324.95) ; v1(3672.5,1650) 3672.5,1657.5 IC3.4
  Bottom Layer w15: v1(3100.05,324.95) 3105.1,330 3255,330 3672.5,747.5 v1(3672.5,1650)
NetIC3_6: IC3.6 IC4.20 | length 2349.7
  Top Layer w15: IC4.20 2909.49,278.48 2987.97,200 v1(3265,200)
  Bottom Layer w15: v1(3265,200) 3322.5,257.5 3322.5,267.6 4015,960.1 IC3.6
NetIC3_7: IC3.7 IC4.21 | length 2333
  Top Layer w15: IC4.21 2942.26,328.25 2942.26,301.97 2994.23,250 v1(3365,250)
  Bottom Layer w15: v1(3365,250) 4115,1000 IC3.7
NetIC3_8: IC3.8 V4.10 | length 1231.2
  Top Layer w25: V4.10 4204.62,2688.6 4204.62,2460.38 4272.72,2392.28 4340.22,2392.28 v1(4345,2387.5) ; IC3.8 v1(4345,1800)
  Bottom Layer w25: v1(4345,1800) v1(4345,2387.5)
NetIC3_9: IC3.9 V4.9 | length 951.7
  Top Layer w25: V4.9 4124.14,2947.05 4295,2776.18 v1(4295,2480)
  Bottom Layer w25: IC3.9 4215,2400 v1(4295,2480)
NetIC3_10: IC3.10 V4.5 | length 1880.2
  Top Layer w25: V4.5 3739.49,3270.96 3808.8,3340.27 3888.53,3420 4055,3420 4295,3180 v1(4295,2870)
  Bottom Layer w25: IC3.10 4115,2389.61 4295,2569.61 v1(4295,2870)
NetIC3_11: IC3.11 V4.6 | length 2311.4
  Top Layer w25: v1(3325,2180) 3935,2180 IC3.11
  Bottom Layer w25: v1(3325,2180) 3415,2270 3415,3100 3695,3380 3819.14,3380 3896.97,3302.17 V4.6
NetIC3_13: IC3.13 V4.8 | length 1846.8
  Top Layer w25: v1(3815,1940) v1(4145,1940)
  Bottom Layer w25: v1(3815,1940) IC3.13 ; V4.8 4267.03,2980.53 4267.03,2979.93 4342.5,2904.46 4342.5,2460.32 4267.03,2384.85 4267.03,2062.03 v1(4145,1940)
NetIC3_14: IC3.14 V4.7 | length 1746.4
  Bottom Layer w25: IC3.14 3662.97,2047.97 3493.45,2047.97 3462.97,2078.45 3462.97,2121.55 3565,2223.58 3565,2768.49 3656.24,2859.73 3710.34,2859.73 3795.73,2945.12 3795.73,3003.29 V4.7
NetIC3_15: IC3.15 V4.11 | length 714.6
  Bottom Layer w25: IC3.15 4054.45,2539.45 4054.45,2566.25 4055.01,2566.81 4055.01,2631.53 V4.11
NetIC3_16: IC3.16 V4.2 | length 734.3
  Bottom Layer w25: IC3.16 3615,2200 3615,2709.63 3670.59,2765.22 V4.2
NetIC4_1: IC4.1 R21.1 T7.3 | length 2770.7
  Top Layer w15: R21.1 2330,1235 2395,1300 2461.21,1300 2470,1291.21 2470,775 2537.52,707.48 IC4.1
  Top Layer w25: R21.1 1765.54,1234.46 1765.54,1171.63 v1(1766.09,1171.09)
  Bottom Layer w25: T7.3 768.13,463.13 768.13,474.18 1131.25,837.3 1165.52,837.3 1499.31,1171.09 v1(1766.09,1171.09)
NetIC4_2: IC4.2 IC8.3 | length 3086.1
  Top Layer w15: IC4.2 2726.21,675.98 2735,684.77 v1(2735,686.99) ; v1(3305,1290) 3415,1400 v1(4585,1400)
  Bottom Layer w15: v1(2735,686.99) 2741.99,686.99 2845,790 3245,790 3305,850 v1(3305,1290) ; v1(4585,1400) 4915,1730 IC8.3
NetIC4_3: IC4.3 IC8.6 | length 3380.3
  Top Layer w15: IC4.3 2789.49,644.49 v1(2835,690) ; v1(3385,1280) 4734.29,1280 5085.69,1631.41 5086.41,1631.41 5213.21,1758.21 5213.21,1798.21 IC8.6
  Bottom Layer w15: v1(2835,690) 2910,765 3310,765 3385,840 v1(3385,1280)
NetIC4_4: IC4.4 IC8.7 | length 3439.2
  Top Layer w15: IC4.4 2876.21,612.99 2885,621.78 v1(2885,624) ; v1(3465,1220) 4709.64,1220 5064.64,1575 5140,1575 5315,1750 IC8.7
  Bottom Layer w15: v1(2885,624) 2889,624 3005,740 3320.36,740 3465,884.64 v1(3465,1220)
NetIC4_5: IC4.5 R23.1 | length 2120.1
  Top Layer w15: IC4.5 2916.5,581.5 v1(2965,630) ; v1(3575,1322.5) 3582.5,1330 3583.75,1328.75 4158.75,1328.75 R23.1
  Bottom Layer w15: v1(2965,630) 2975,630 3060,715 3371.21,715 3575,918.79 v1(3575,1322.5)
NetIC4_14: IC4.14 R9.1 | length 4068.2
  Top Layer w15: v1(365,1450) 365,300 465,200 2640,200 2719.24,279.24 2719.24,328.25 IC4.14 ; R9.1@506.7,1693.3 R9.1 v1(515,1750)
  Bottom Layer w15: v1(365,1450) 365,1600 v1(515,1750)
NetIC4_15: IC4.15 R7.1 | length 4335.8
  Top Layer w15: R7.1 705,1625 440,1625 315,1500 315,300 465,150 2633.32,150 2750.73,267.41 2750.73,328.25 IC4.15
NetIC4_16: IC4.16 K1.1 R6.1 | length 4123
  Top Layer w15: R6.1 265,300 465,100 K1.1 2637.03,122.03 2647.03,122.03 2783.5,258.5 IC4.16
NetIC4_17: IC4.17 K1.2 | length 270.9
  Top Layer w15: K1.2 2716.79,101.79 2716.79,141.79 2815,240 IC4.17
NetIC4_18: IC4.18 K1.5 R11.1 | length 780.2
  Top Layer w15: IC4.18 2846.5,268.5 K1.5 ; K1.5@3008.93,100 3390.24,100 3450.24,160 R11.1
NetIC4_24: IC4.24 R12.2 | length 690.5
  Top Layer w15: IC4.24 3130.63,424.02 3262.14,292.5 3382.6,292.5 3434.34,240.77 3601,240.77 3625.24,265 R12.2
NetIC4_37: IC4.37 JP1.2 R14.2 | length 798.4
  Top Layer w15: IC4.37 2879.27,771.75 2879.27,814.27 2965,900 JP1.2
  Top Layer w25: R14.2 2765,1250 JP1.2
NetIC4_38: IC4.38 IC9.3 | length 3862.3
  Top Layer w15: IC4.38 2847.77,771.75 2847.77,818.12 2867.26,837.61 2867.26,838.32 2868.5,839.57 2868.5,882.08 2851,899.58 v1(2851,951.56) ; v1(3164.95,960.05) 3165,960.1 3165,1090.1 3234.9,1160 4685,1160 5000,1475 5815,1475 6015,1675 IC9.3
  Bottom Layer w15: v1(2851,951.56) 2851.95,952.5 3157.4,952.5 v1(3164.95,960.05)
NetIC4_39: IC4.39 IC9.6 | length 4384.3
  Top Layer w15: IC4.39 2815,840 2826,851 v1(2826,856.46) ; v1(3175.05,852.5) 3177.55,850 3624.18,850 3854.18,1080 5170,1080 5300,1210 5300,1300 5375,1375 6056.51,1375 6462.03,1780.52 6462.03,1819.48 6434.48,1847.03 6362.03,1847.03 IC9.6
  Bottom Layer w15: v1(2826,856.46) 2827.99,854.48 3173.07,854.48 v1(3175.05,852.5)
NetIC4_40: IC4.40 IC9.7 | length 4211
  Top Layer w15: IC4.40 2783.5,888.68 2794.41,899.59 v1(2794.41,909.06) ; v1(3225.05,899.95) 3614.95,899.95 3820,1105 5155,1105 5275,1225 5275,1314.64 5360.36,1400 6046.15,1400 6408.79,1762.64 6408.79,1793.79 IC9.7
  Bottom Layer w15: v1(2794.41,909.06) 3215.94,909.06 v1(3225.05,899.95)
NetIC4_41: IC4.41 IC9.4 | length 4040.2
  Top Layer w15: v1(2722.5,897.25) 2722.5,889.09 2752.01,859.58 IC4.41 ; v1(3235,1100) 3265,1130 5140,1130 5250,1240 5250,1325 5350,1425 5885,1425 6115,1655 IC9.4
  Bottom Layer w15: v1(2722.5,897.25) 2925.25,1100 v1(3235,1100)
NetIC4_42: IC4.42 R15.2 S1.1 | length 531.5
  Top Layer w15: IC4.42 2720.51,839.13 2680,879.64 2680,965 S1.1
  Top Layer w25: R15.2 S1.1
NetIC4_43: IC4.43 R8.1 | length 804.6
  Top Layer w15: R8.1 2460.36,1360 2530.77,1289.59 2530.77,993.52 2689.02,835.27 IC4.43
NetIC4_44: IC4.44 R18.1 T6.3 | length 1795.6
  Top Layer w15: R18.1 v1(1765,525) ; v1(2555,810) 2595,770 2654.45,770 2654.92,770.47 IC4.44
  Top Layer w25: v1(1675,460) 1677.5,462.5 1762.5,462.5 R18.1
  Bottom Layer w15: v1(1765,525) 2050,810 v1(2555,810)
  Bottom Layer w25: T6.3 1118.13,456.87 1118.13,445.82 1147.12,416.83 1148.17,416.83 1165,400 1615,400 v1(1675,460)
NetIC7_2: IC7.2 R16.2 T5.1 | length 1098.2
  Top Layer w35: T5.1 5121.77,290 5351.77,60 5544.5,60 5565,80.5 IC7.2
NetIC8_1: IC8.1 V5.4 | length 1519.6
  Bottom Layer w25: IC8.1 4715,1927.43 4592.97,2049.45 4592.97,2150.55 4745,2302.57 4745,2926.62 V5.4
NetIC8_2: IC8.2 V5.3 | length 1359.4
  Bottom Layer w25: IC8.2 4815,1876.92 4627.97,2063.95 4627.97,2136.05 4795,2303.08 4795,2807.33 4934.72,2947.05 V5.3
NetIC8_8: IC8.8 V5.10 | length 1197.6
  Top Layer w25: V5.10 5465,2700.23 5465,2512.18 5547.18,2430 v1(5625,2430)
  Bottom Layer w25: IC8.8 5415,1970 5525,2080 5525,2320 5625,2420 v1(5625,2430)
NetIC8_9: IC8.9 V5.9 | length 988.2
  Top Layer w25: V5.9 5396.14,2947.05 5433.82,2909.36 5433.82,2908.57 5575,2767.39 v1(5575,2520)
  Bottom Layer w25: IC8.9 5415,2360 v1(5575,2520)
NetIC8_10: IC8.10 V5.5 | length 1929.6
  Top Layer w25: V5.5 5011.49,3270.96 5080.8,3340.27 5170.53,3430 5325,3430 5575,3180 v1(5575,2860)
  Bottom Layer w25: IC8.10 5315,2332.82 5575,2592.82 v1(5575,2860)
NetIC8_11: IC8.11 V5.6 | length 2370.7
  Top Layer w25: v1(4505,2170) 5145,2170 IC8.11
  Bottom Layer w25: v1(4505,2170) 4695,2360 4695,3100 4975,3380 5091.14,3380 5168.97,3302.17 V5.6
NetIC8_13: IC8.13 V5.8 | length 1871.4
  Top Layer w25: v1(5015,1950) v1(5195,1950)
  Bottom Layer w25: v1(5015,1950) IC8.13 ; v1(5195,1950) 5338.58,1950 5475,2086.42 5475,2347.18 5622.5,2494.68 5622.5,2917.35 5415.64,3124.21 V5.8
NetIC8_14: IC8.14 V5.7 | length 1776.3
  Bottom Layer w25: IC8.14 4862.97,2047.97 4693.45,2047.97 4662.97,2078.45 4662.97,2121.55 4845,2303.58 4845,2776.49 4928.24,2859.73 4982.34,2859.73 5067.73,2945.12 5067.73,3003.29 V5.7
NetIC8_15: IC8.15 V5.11 | length 743.9
  Bottom Layer w25: IC8.15 4815,2109.22 5326.45,2620.66 V5.11
NetIC8_16: IC8.16 V5.2 | length 764.2
  Bottom Layer w25: IC8.16 4895,2280 4895,2701.63 4942.59,2749.22 V5.2
NetIC9_1: IC9.1 V6.4 | length 1498.8
  Bottom Layer w25: IC9.1 5815,1900 5685,2030 5685,2170 5735,2220 5735,2882.62 V6.4
NetIC9_2: IC9.2 V6.3 | length 1334.6
  Bottom Layer w25: IC9.2 5915,1860 5725,2050 5725,2150 5785,2210 5785,2763.33 5968.72,2947.05 V6.3
NetIC9_8: IC9.8 V6.10 | length 1096.5
  Top Layer w25: V6.10 6525,2674.23 6525,2450 v1(6625,2350)
  Bottom Layer w25: IC9.8 6515,1976.92 6625,2086.92 v1(6625,2350)
NetIC9_9: IC9.9 V6.9 | length 957.5
  Top Layer w25: V6.9 6430.14,2947.05 6467.82,2909.36 6467.82,2908.57 6605,2771.39 v1(6605,2510)
  Bottom Layer w25: IC9.9 6515,2420 v1(6605,2510)
NetIC9_10: IC9.10 V6.5 | length 1888.3
  Top Layer w25: V6.5 6045.49,3270.49 6112.68,3337.68 6112.68,3338.15 6194.53,3420 6365,3420 6605,3180 v1(6605,2860)
  Bottom Layer w25: IC9.10 6415,2389.61 6605,2579.61 v1(6605,2860)
NetIC9_11: IC9.11 V6.6 | length 2297.4
  Top Layer w25: v1(5635,2170) 6245,2170 IC9.11
  Bottom Layer w25: v1(5635,2170) 5635,2176.76 5647.5,2189.26 5647.5,2192.5 5685,2230 5685,3050 6015,3380 6125.14,3380 6202.97,3302.17 V6.6
NetIC9_13: IC9.13 V6.8 | length 1659.8
  Bottom Layer w25: IC9.13 6167.03,2047.97 6536.55,2047.97 6575,2086.42 6575,2412.82 6652.5,2490.32 6652.5,2901.06 V6.8
NetIC9_14: IC9.14 V6.7 | length 1748.9
  Bottom Layer w25: IC9.14 5962.97,2047.97 5793.45,2047.97 5762.97,2078.45 5762.97,2121.55 5835,2193.58 5835,2732.49 5962.24,2859.73 6016.34,2859.73 6101.73,2945.12 6101.73,3003.29 V6.7
NetIC9_15: IC9.15 V6.11 | length 717.1
  Bottom Layer w25: IC9.15 6361.01,2546.01 6361.01,2631.53 V6.11
NetIC9_16: IC9.16 V6.2 | length 736.8
  Bottom Layer w25: IC9.16 5885,2170 5885,2678.29 V6.2
NetLA1_1: LA1.1 T3.3 | length 1602.1
  Bottom Layer w25: T3.3 2211.87,1553.13 2211.87,1653.13 2125,1740 2125,2990 2185,3050 LA1.1@2225,3050
NetLA1_2: LA1.2 R3.1 | length 418.5
  Top Layer w25: R3.1 LA1.2@2225,2833.46
NetLA2_1: LA2.1 T8.3 | length 1593.8
  Bottom Layer w25: T8.3 4511.87,1553.13 4511.87,1653.13 4437.67,1727.33 4437.67,2992.67 4495,3050 LA2.1
NetLA2_2: LA2.2 R24.1 | length 423.9
  Top Layer w25: R24.1@4534.5,2410.5 LA2.2@4534.5,2832.96
  Top Layer w35: LA2.2@4534,2833.46 LA2.2@4534.5,2832.96 ; R24.1@4534.5,2410.5 R24.1
NetLED1_1: LED1.1 R12.1 | length 327.5
  Top Layer w15: R12.1 3959.06,135 LED1.1
NetLED2_1: LED2.1 R29.2 | length 839.8
  Top Layer w25: R29.2 v1(710,2415)
  Bottom Layer w25: LED2.1 628.52,2804.47 695.47,2804.47 757,2866 820,2866 874.26,2811.74 874.26,2579.26 v1(710,2415)
NetLED3_1: LED3.1 R30.2 | length 1204.2
  Top Layer w25: R30.2 1743.24,2415 1748.24,2420 v1(1755,2420)
  Bottom Layer w25: LED3.1 1654.06,2801.97 1669.11,2817.03 1672.03,2817.03 1717.23,2862.23 1717.23,2981.54 1759.37,3023.68 1888.32,3023.68 1955,2957 1955,2620 v1(1755,2420)
NetLED4_1: LED4.1 R31.2 | length 1162.9
  Top Layer w25: R31.2 3050,2415 v1(3055,2420)
  Bottom Layer w25: LED4.1 2924.06,2801.97 2987.54,2865.45 2987.54,2972.3 3035.96,3020.73 3142.73,3020.73 3215,2948.46 3215,2580 v1(3055,2420)
NetLED5_1: LED5.1 R32.2 | length 1173.8
  Top Layer w25: R32.2 4050,2415 v1(4055,2420)
  Bottom Layer w25: LED5.1 3964.06,2801.97 4024.54,2862.45 4024.54,2975.3 4069.96,3020.73 4176.73,3020.73 4247.5,2949.96 4247.5,2850.32 4248.2,2849.63 4248.2,2613.2 v1(4055,2420)
NetLED6_1: LED6.1 R33.2 | length 1213.5
  Top Layer w25: R33.2 5330,2415 v1(5335,2420)
  Bottom Layer w25: LED6.1 5234.06,2801.97 5295.54,2863.45 5295.54,2974.3 5341.96,3020.73 5469.63,3020.73 5520.2,2970.16 5520.2,2605.2 v1(5335,2420)
NetLED7_1: LED7.1 R34.2 | length 1237.9
  Top Layer w25: R34.2 6360,2415 v1(6365,2420)
  Bottom Layer w25: LED7.1 6264.06,2801.97 6324.74,2862.66 6324.74,2975.1 6370.37,3020.73 6482.73,3020.73 6554.2,2949.26 6554.2,2609.2 v1(6365,2420)
NetMOD1_1: MOD1.1 R10.1 | length 261.3
  Top Layer w25: MOD1.1 1574.8,734.8 R10.1
NetMOD1_4: MOD1.4 MOD1.19 | length 712
  Top Layer w25: MOD1.19 664.97,883.65 723.85,883.65 v1(725,882.5) ; v1(1120.2,884.8) MOD1.4
  Bottom Layer w25: v1(725,882.5) 797.5,810 1045.39,810 v1(1120.2,884.8)
NetMOD1_7: MOD1.7 R20.1 | length 261.3
  Top Layer w25: MOD1.7 1313.92,1234.9 1574.9,1234.9 R20.1
NetMOD1_17: MOD1.17 R28.1 | length 180.6
  Top Layer w25: R28.1 529.76,1060 534,1055.77 534,1054.64 598.62,990.02 658.6,990.02 MOD1.17
NetMOD1_18: MOD1.18 R27.1 | length 768
  Top Layer w25: R27.1 500.24,1475 496,1470.77 430,1404.76 430,1020 515.2,934.8 MOD1.18
NetMOD1_21: MOD1.21 R22.1 T7.1 | length 1018.6
  Top Layer w25: v1(595,445) 500.24,445 496,449.23 420,525.24 420,735.13 469.67,784.8 MOD1.21
  Bottom Layer w25: v1(595,445) 718.95,445 763.95,400 843.52,400 858.17,414.64 858.17,453.17 T7.1
NetMOD1_22: MOD1.22 R19.1 T6.1 | length 1233.5
  Top Layer w25: MOD1.22 951.25,734.8 1208.17,477.88 1208.17,466.83 T6.1 1425,670 R19.1
NetP1_1: P1.1 P1.3 R13.1 | length 878.7
  Top Layer w35: P1.3 6066.57,398.43 P1.1 6315,942.13 R13.1
NetR1_1: R1.1 V1.1 | length 231.8
  Top Layer w25: R1.1 365,2580 400.55,2615.55 V1.1@400.55,2632.09
NetR2_1: R2.1 V2.1 | length 225.8
  Top Layer w25: R2.1 1415,2569.32 1428.9,2583.22 V2.1@1428.9,2635.04
NetR4_1: R4.1 V3.1 | length 221.5
  Top Layer w25: V3.1 2704.93,2631.53 2704.93,2578.23 2715,2568.16 R4.1
NetR5_1: R5.1 V4.1 | length 227.2
  Top Layer w25: R5.1 3715,2564.32 3739.49,2588.81 V4.1
NetR6_2: R6.2 T1.2 | length 185
  Top Layer w25: R6.2 T1.2
NetR7_2: R7.2 T2.2 | length 185
  Top Layer w25: R7.2 T2.2
NetR8_2: R8.2 T3.2 | length 208.6
  Top Layer w15: R8.2 R8.2@2210,1374.76
  Top Layer w25: T3.2 2165,1419.76 R8.2@2210,1374.76
NetR9_2: R9.2 T4.2 | length 185
  Top Layer w25: R9.2 T4.2
NetR23_2: R23.2 T8.2 | length 384.5
  Top Layer w25: R23.2 4179.76,1465 4307.93,1593.17 4444.99,1593.17 4461.87,1576.28 4461.87,1553.13 T8.2
NetR25_1: R25.1 V5.1 | length 217.6
  Top Layer w25: R25.1 4965,2562.74 4990.7,2588.44 V5.1@4990.7,2621.93
NetR26_1: R26.1 V6.1 | length 250
  Top Layer w25: R26.1 5965,2552.6 V6.1@6044.49,2632.09
NetT1_3: T1.3 V1.2 | length 826.5
  Bottom Layer w25: T1.3 311.87,2003.13 311.87,2073.13 255,2130 255,2690 331.65,2766.65 V1.2@331.65,2769.88
NetT2_3: T2.3 V1.10 | length 900.9
  Bottom Layer w25: V1.10@784.41,2769.88 784.41,2726.61 805.36,2705.66 805.36,2577.54 662.5,2434.68 662.5,2295.8 815,2143.3 T2.3
NetT4_3: T4.3 V1.11 | length 694.4
  Bottom Layer w25: T4.3 565,2460 715.51,2610.51 V1.11@715.51,2632.09
pads on no net: IC4.12 IC4.13 IC4.23 IC4.25 IC4.26 IC4.27 IC4.33 IC4.34 LA1.3 LA2.3 MOD1. MOD1.2 MOD1.8 MOD1.10 MOD1.11 MOD1.12 MOD1.13 MOD1.14 MOD1.15 MOD1.16 V1.0 V1.3 V1.4 V1.5 V1.6 V1.7 V1.8 V1.9 V1.12 V2.0 V2.12 V3.0 V3.12 V4.0 V4.12 V5.0 V5.12 V6.0 V6.12

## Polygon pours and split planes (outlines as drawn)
GND on Bottom Layer "GND" (solid, pour order 2): 0,0 0,3700 6761,3700 6761,0
+5V on Top Layer "+5V" (solid, pour order 1): 0,0 0,3700 6761,3700 6761,0

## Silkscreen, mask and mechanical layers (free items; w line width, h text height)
Top Overlay:
  circle w10: c4015,130 r3.35
  lines w20: 0,0 0,3700 6761,3700 6761,0 0,0
  text "Damian Moris (11900357): Nixie Klok 24/04/2020" at 2350,1425 h60
  text "GND" at 6455,780 h60
  text "9-15V" at 6325,160 h60
Bottom Overlay:
  circle w10: c6264.55,2847.83 r0.96
  circle w10: c5234.6,2846.4 r0.48
  circle w10: c3965.18,2847.9 r1.07
  circle w10: c2925,2850 r3.51
  circle w10: c625,2850 r3.51
  circle w10: c1655,2850 r3.51
  circle w10: c2265,2770 r5.1
  circle w10: c4585,2770 r5.1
